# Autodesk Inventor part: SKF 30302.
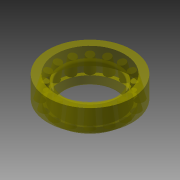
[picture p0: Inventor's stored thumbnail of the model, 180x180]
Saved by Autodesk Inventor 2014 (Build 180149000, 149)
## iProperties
Created: 2001-02
Part Number: SKF 30302.
Material: Steel, Mild
Description: Bearing SKF 30302.
Document SubType Name: Modeling
Density: 7.86 g/cm^3
Appearance: Yellow(Clear)
ProtocolID: P00020918081535475
Protocol: P00020918081535475<@PID>[Version]<@EL>Version=2.2<@EL>[Synchronize]<@EL>ChangedVars=<@EL>[Calc]<@EL>ScnVisible=0<@EL>WizardMode=2<@EL>CalcName=BEARINGS<@EL>Opti
Control State: 0
Master: False
Checked Out: False
Shininess: 20.0
Length Units: 11269
Angle Units: 11279
Time Units: 11290
Mass Units: 11283
Length Display Precision: 3
Angle Display Precision: 2
BOM1: Bearing
BOM2: SKF 30302
Density: 7.86
Volumn: 10.214056141118272
Area: 88.6561878138125
PropertySet Name: Model Information
Author: PaulN
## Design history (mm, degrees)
node "WorkPlane4"
node "WorkPlane1"
workplane "Work Plane3"
node "WorkPlane2"
node "Sketch1"
node "WorkPoint1"
node "Sketch2"
node "WorkPoint2"
extrude "ExtrusionBlind1" new body distance "d3" = 23 (= prf_b); taper "d4" = 0 deg
  node "Sketch3" dims "d2" = 72.5 (= msp_dd2)
node "WorkAxis1"
sketch "Sketch4"
  geometry: C1 r 36.25 at (0, 0) reference
hole "Hole1" sketch "Sketch4" diameter "d6" = 55 (= prf_d); stored, may be unused: countersink angle "d10" = 60 deg, drill point angle "d12" = 118 deg; dims "d7" = 6, "d8" = 4, "d9" = 2, "d11" = 8
sketch "Sketch5"
  geometry: L1 (38.121, 23)-(34.062, 23); L2 (34.062, 23)-(34.062, 23.734); L3 (30.465, 22.969)-(34.062, 23.734); L4 (30.465, 22.969)-(33.285, 5.171); L5 (33.285, 5.171)-(38.121, 6.199); L6 (38.121, 23)-(38.121, 6.199); L7 (31.875, 14.07)-(36.25, 15); L8 (34.823, 21.715)-(37.782, 7.79); L9 (0, 15.439)-(0, -16.364); L10 (-36.25, 23)-(36.25, 23) reference; L11 (-36.25, 0)-(36.25, 0) reference; L12 (0, 29.364)-(0, -16.364); L13 (0, -25.509)-(0, 38.509) reference
  constraints: 20 end point, 3 collinear, 3 parallel, 2 perpendicular, 2 point on line, 2 vertical, 1 horizontal, 1 midpoint
  dimensions: "d14" = 12 deg angle of L9 L8 (= prf_alfa); "d17" = 17.7978 vertical distance of L3.start L4.end (computed from msp_l0, prf_alfa, msp_ang); "d37" = 72.5 diameter of L7.end L12 (= msp_mdtds); "d42" = 8.8989 vertical distance of L4.end L7.start (= d23); "d49" = 2.9944 deg angle of L8 L4 (= msp_ang); "d54" = 15 distance from line of L11 L7.end (= 0.5 x prf_t); "d55" = 4.375 horizontal distance of L7.start L7.end (= 0.5 x msp_dd0); "d56" = 68.125 diameter of L1.end L13 (= msp_mdtds - 0.5 x msp_dd0)
revolve "RevolutionFull1" sketch "Sketch5" stored, may be unused: angle "d18" = 360 deg
sketch "Sketch6"
  geometry: L1 (33.285, 5.171)-(38.121, 6.199); L2 (33.285, 5.171)-(30.465, 22.969); L3 (30.465, 22.969)-(34.379, 23.801); L4 (38.121, 6.199)-(34.379, 23.801); L5 (34.614, 22.696)-(37.676, 8.293); L6 (31.875, 14.07)-(36.25, 15); L7 (0, 29.364)-(0, -16.364); L8 (-36.25, 0)-(36.25, 0) reference; L9 (38.121, 6.199)-(34.379, 23.801); L10 (0, -25.509)-(0, 38.509) reference; L11 (33.285, 5.171)-(30.465, 22.969) reference; L12 (36.25, 5.801)-(33.285, 5.171) reference; L13 (30.465, 22.969)-(30.611, 23) reference
  constraints: 17 end point, 3 point on line, 2 collinear, 2 midpoint, 2 parallel, 1 perpendicular
  dimensions: "d20" = 12 deg angle of L7 L5 (= prf_alfa); "d23" = 8.8989 vertical distance of L6.start L1.start (computed from msp_ang, prf_alfa, msp_l0); "d46" = 72.5 diameter of L6.end L7 (= d37); "d47" = 17.7978 vertical distance of L1.start L2.end (= d17)
revolve "RevolutionFull2" sketch "Sketch6" stored, may be unused: angle "d24" = 360 deg
pattern_circular "PolarArray1" dims angle "d27" = 360 deg
sketch "Sketch7"
  geometry: L1 (45, 7)-(43.017, 7); L2 (45, 30)-(45, 7); L3 (36.857, 30)-(45, 30); L4 (43.017, 7)-(36.857, 30); L5 (-36.25, 0)-(36.25, 0) reference; L6 (0, 29.364)-(0, -16.364); L7 (0, 29.364)-(0, -16.364); L8 (0, -25.636)-(0, 39.273) reference; L9 (42.956, 7.227)-(38.294, 24.633) reference; L10 (35, 30)-(-35, 30) reference
  constraints: 12 end point, 2 horizontal, 1 collinear, 1 parallel, 1 vertical
  dimensions: "d29" = 23 distance of L2.start L1.start (= prf_cc); "d44" = 90 diameter of L2 L6 (= prf_dd); "d45" = 30 distance between parallel lines of L5 L3 (= prf_t); "d63" = 0.0001 distance between parallel lines of L4 L9
fillet "Fillet2" dims "d33" = 1.5 (= prf_r)
fillet "Fillet3" dims "d34" = 1.5 (= prf_r)
revolve "Revolution4" stored, may be unused: angle "d62" = 90 deg
body "Solid1"
other parameters: "prf_b" = 23 [user parameter; used in 1 equation term], "prf_dd" = 90 [user parameter; used in 4 equation terms], "prf_d" = 55 [user parameter; used in 4 equation terms], "msp_dd2" = 72.5 (= 0.5 x prf_d + 0.5 x prf_dd) [user parameter; used in 1 equation term], "prf_t" = 30 [user parameter; used in 3 equation terms], "prf_r" = 1.5 [user parameter; used in 2 equation terms], "prf_cc" = 23 [user parameter; used in 2 equation terms], "msp_dd0" = 8.75 (= -0.25 x prf_d + 0.25 x prf_dd) [user parameter; used in 5 equation terms], "msp_mdtds" = 72.5 (= 0.5 x prf_d + 0.5 x prf_dd) [user parameter; used in 3 equation terms], "prf_alfa" = 12 deg [user parameter; used in 5 equation terms], "msp_l0" = 18.4 (= 0.8 x prf_cc) [user parameter; used in 3 equation terms], "msp_ang" = 2.9944 deg (computed from msp_l0, msp_dd0) [user parameter; used in 4 equation terms], "msp_pom2" = 2.61702 (= prf_alfa + msp_ang) [user parameter; used in 1 equation term], "msp_dd0a" = 4.52921 (computed from msp_dd0, msp_pom2) [user parameter], "d1" = 31 (derived), "d5" = 0, "d13" = 12 deg (derived), "d15" = 0.01098 (derived), "d16" = 9.38802 (derived), "d19" = 12 deg (derived), "d21" = 0.01098 (derived), "d22" = 4.69401 (derived), "d28" = 12 (derived), "d30" = 2.10538 (derived)
